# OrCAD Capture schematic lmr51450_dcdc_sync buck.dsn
size C
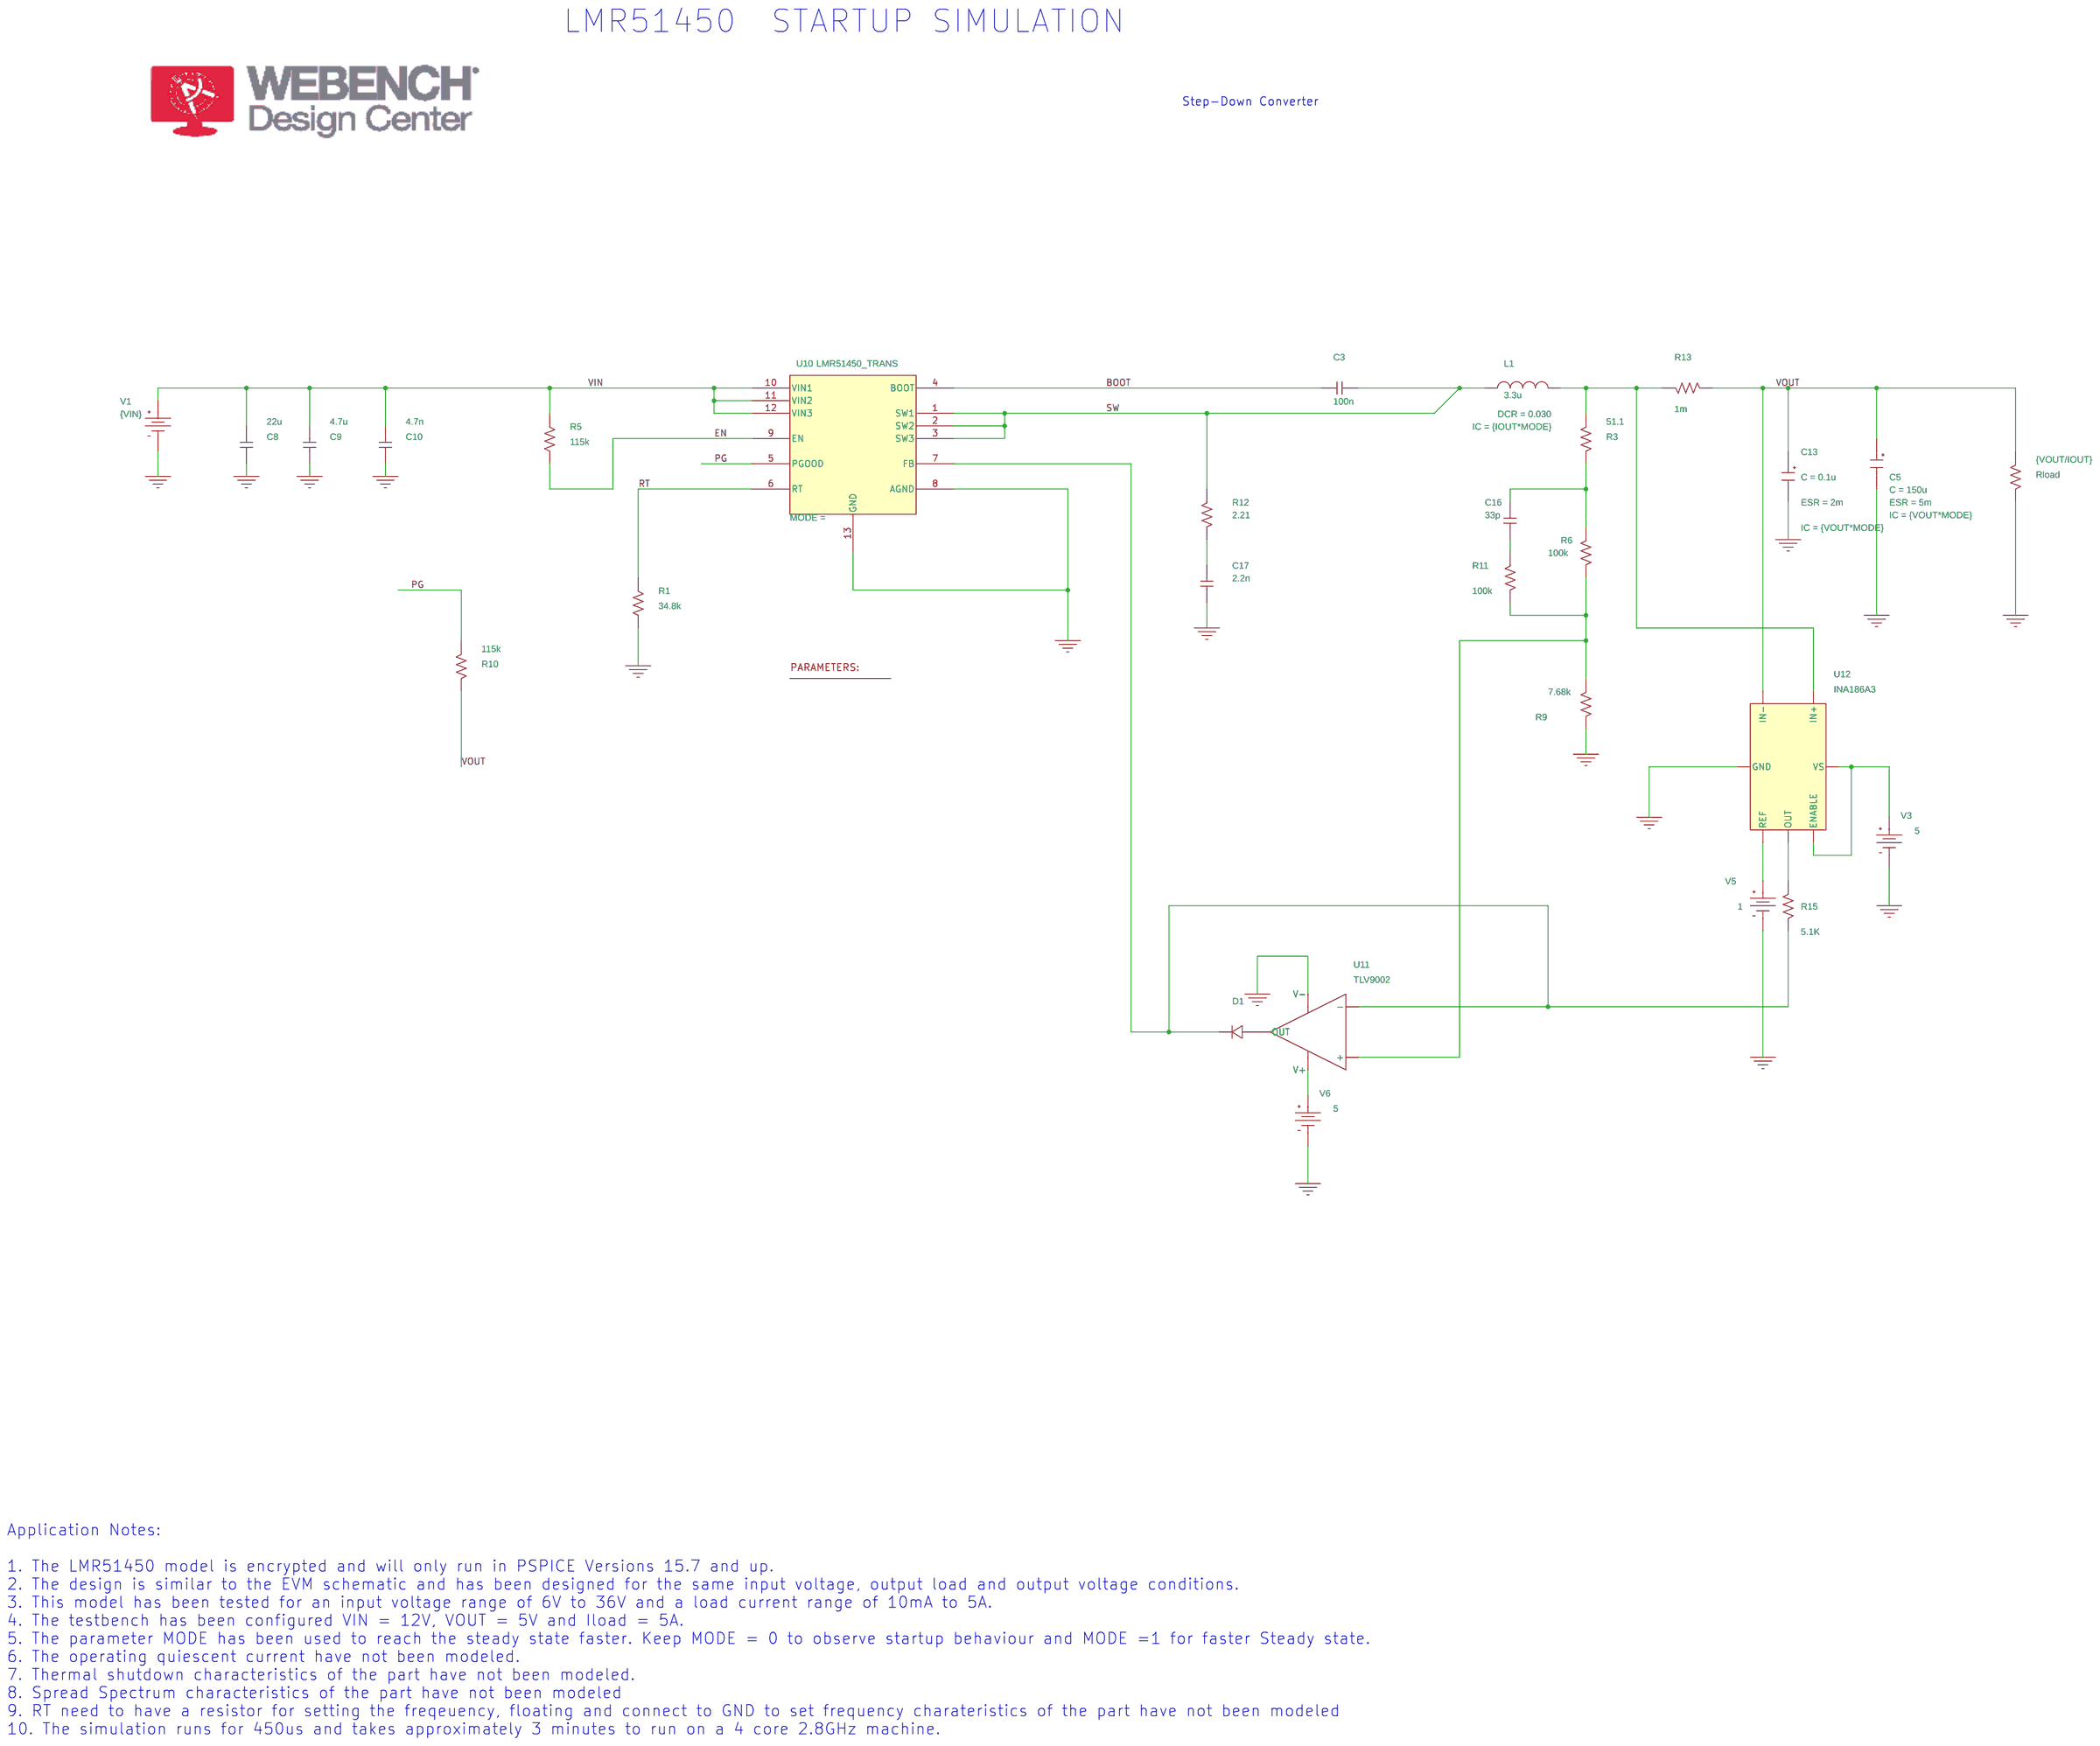
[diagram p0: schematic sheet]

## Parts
1  PARAM
C3  100n  [RAD/CK05]
C5  CESR
C8  22u  [RAD/CK05]
C9  4.7u  [RAD/CK05]
C10  4.7n  [RAD/CK05]
C13  CESR
C16  33p  [RAD/CK05]
C17  2.2n  [RAD/CK05]
D1  POWER_DIODE_P
L1  3.3u  [DISC/.350x.175/LS.200x.100/.034]
R1  34.8k  [AX/RC05]
R3  51.1  [AX/RC05]
R5  115k  [AX/RC05]
R6  100k  [AX/RC05]
R9  7.68k  [AX/RC05]
R10  115k  [AX/RC05]
R11  100k  [AX/RC05]
R12  2.21  [AX/RC05]
R13  1m  [AX/RC05]
R15  5.1K  [AX/RC05]
Rload  {VOUT/IOUT}  [AX/RC05]
U10  LMR51450_TRANS
U11  TLV9002
U12  INA186A3
V1  VDC
V3  VDC
V5  VDC
V6  VDC

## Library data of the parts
1 = PARAM: IOUT: 3; VIN: 12; VOUT: 11.2
C3 C8-C10 C16 C17 = c
C5 = CESR_0: C: 150u; ESR: 5m; IC: {VOUT*MODE}; PSpiceTemplate: X^@REFDES %IN %OUT @MODEL PARAMS:  ?C|C=@C||C=100u|  ?ESR|ESR=@ESR||ESR=0.01| ?X|X=@X||X=2|  ?IC|IC=@IC||IC=2|; X: 1
C13 = CESR_0: C: 0.1u; ESR: 2m; IC: {VOUT*MODE}; PSpiceTemplate: X^@REFDES %IN %OUT @MODEL PARAMS:  ?C|C=@C||C=100u|  ?ESR|ESR=@ESR||ESR=0.01| ?X|X=@X||X=2|  ?IC|IC=@IC||IC=2|; X: 1
D1 = POWER_DIODE_P: CT_ZERO_VOLTS: 4p; IF_SPEC: 0.250; I_REV_LEAK: 2e-6; VJ_KNEE: 0.55; VJ_SPEC: 0.55; V_BR: 40
L1 = L: DCR: 0.030; IC: {IOUT*MODE}
R1 R3 R5 R6 R9-R13 R15 = r
Rload = R
U10 = LMR51450_TRANS
U11 = TLV9002
U12 = INA186A3
V1 = VDC: DC: {VIN}
V3 V6 = VDC: DC: 5
V5 = VDC: DC: 1

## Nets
VIN: C8.1 C9.1 C10.1 R5.1 U10.10(VIN1) U10.11(VIN2) U10.12(VIN3) V1.0(+)
0: C5.3(OUT) C8.2 C9.2 C10.2 C13.3(OUT) C17.1 R1.2 R9.2 Rload.2 U10.8(AGND) U10.13(GND) U11.V- U12.GND V1.1(-) V3.1(-) V5.1(-) V6.1(-)
BOOT: C3.1 U10.4(BOOT)
EN: R5.2 U10.9(EN)
PG: R10.1 U10.5(PGOOD)
RT: R1.1 U10.6(RT)
SW: C3.2 L1.1 R12.1 U10.1(SW1) U10.2(SW2) U10.3(SW3)
VOUT: C5.1(IN) C13.1(IN) R10.2 R13.2 Rload.1 U12.IN-
N14374887: L1.2 R3.1 R13.1 U12.IN+
N14375309: C16.2 R3.2 R6.1
N14375553: R6.2 R9.1 R11.2 U11.+
N14376813: C16.1 R11.1
N14380343: C17.2 R12.2
N14384074: D1.1(2) R15.2 U10.7(FB) U11.-
N14385445: U12.ENABLE U12.VS V3.0(+)
N14389831: R15.1 U12.OUT
N14389873: U12.REF V5.0(+)
N14393403: U11.V+ V6.0(+)
N14394834: D1.0(1) U11.OUT

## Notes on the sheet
- LMR51450  STARTUP SIMULATION
- Step-Down Converter
- Application Notes:
  1. The LMR51450 model is encrypted and will only run in PSPICE Versions 15.7 and up.
  2. The design is similar to the EVM schematic and has been designed for the same input voltage, output load and output voltage conditions.
  3. This model has been tested for an input voltage range of 6V to 36V and a load current range of 10mA to 5A.
  4. The testbench has been configured VIN = 12V, VOUT = 5V and Iload = 5A.
  5. The parameter MODE has been used to reach the steady state faster. Keep MODE = 0 to observe startup behaviour and MODE =1 for faster Steady state.
  6. The operating quiescent current have not been modeled.
  7. Thermal shutdown characteristics of the part have not been modeled.
  8. Spread Spectrum characteristics of the part have not been modeled
  9. RT need to have a resistor for setting the freqeuency, floating and connect to GND to set frequency charateristics of the part have not been modeled
  10. The simulation runs for 450us and takes approximately 3 minutes to run on a 4 core 2.8GHz machine.
